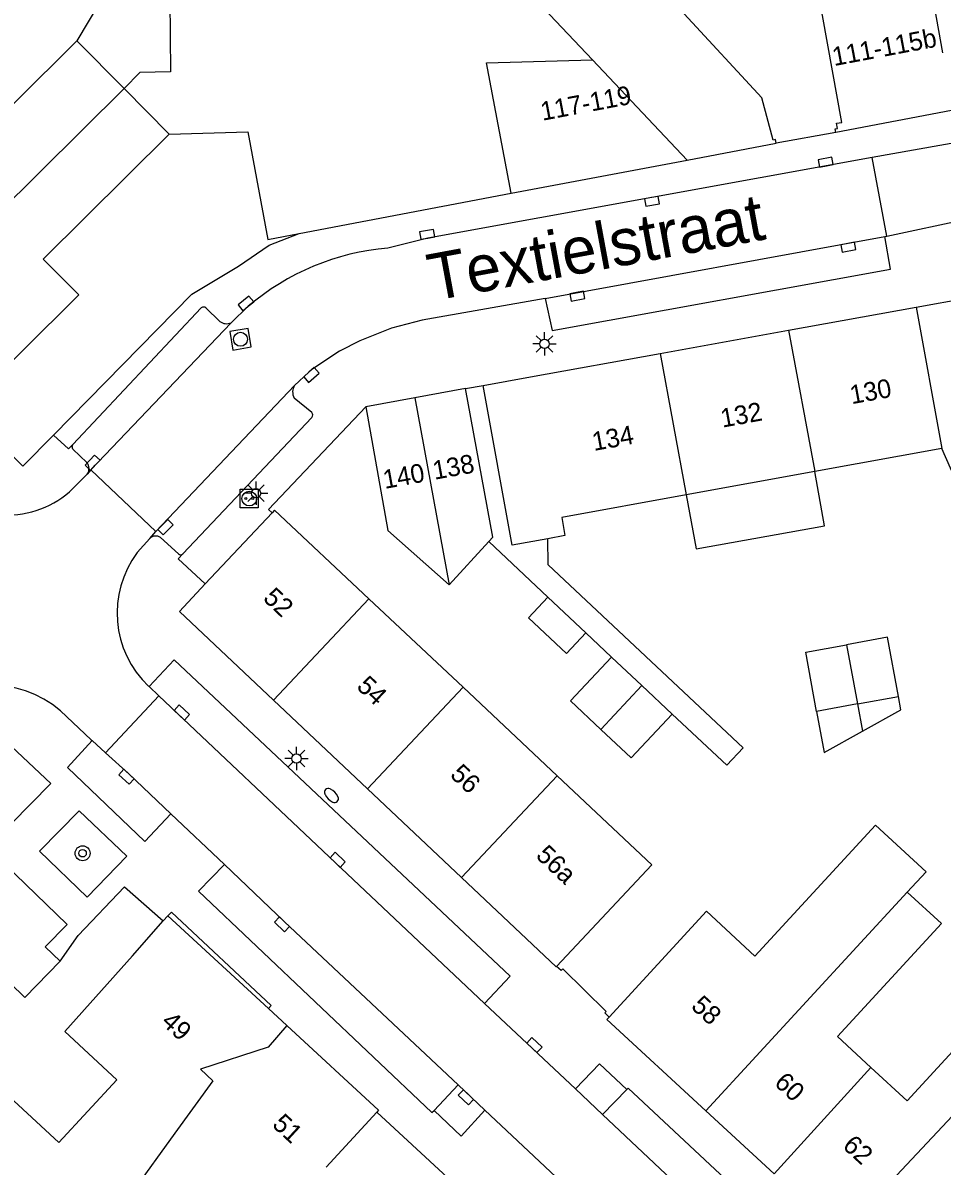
# Model space of a CAD drawing. Extents: x 132573 to 132944, y 398226 to 398676.
# Drawn here: x 132860.9 to 132910.1, y 398438.1 to 398499.2 of the extents above; entities that cross this region are included whole.
import ezdxf

# ---------------------------------------------------------------- set-up
doc = ezdxf.new("R2010")
doc.units = 0
for name, color, linetype in [('gg-afsc-erfafscheiding', 7, 'Continuous'), ('gg-afsc-hekwerk', 7, 'Continuous'), ('gg-afsc-muur', 7, 'Continuous'), ('gg-anno-huisnummerreeks BGT', 7, 'Continuous'), ('gg-anno-openbare ruimte label', 7, 'Continuous'), ('gg-bbg-bijgebouw', 7, 'Continuous'), ('gg-bbg-gedigitaliseerde bebouwing', 7, 'Continuous'), ('gg-bbg-gedigitaliseerde bijgebouw', 7, 'Continuous'), ('gg-bbg-hoofdgebouw', 7, 'Continuous'), ('gg-bbg-luifel en loopbrug', 7, 'Continuous'), ('gg-bbg-onder overbouw', 7, 'Continuous'), ('gg-bbg-pand overbouw', 7, 'Continuous'), ('gg-bbg-tussenscheiding', 7, 'Continuous'), ('gg-knt-verharding', 7, 'Continuous'), ('gg-knt-verharding nz', 7, 'Continuous'), ('gt-symb-boom', 7, 'Continuous'), ('gt-symb-brandkraan', 7, 'Continuous'), ('gt-symb-kolk', 7, 'Continuous'), ('gt-symb-laadpunt elektrisch vervoer', 7, 'Continuous'), ('gt-symb-lichtmast', 7, 'Continuous'), ('gt-symb-rioolschacht', 7, 'Continuous')]:
    doc.layers.add(name, color=color, linetype=linetype)

msp = doc.modelspace()

# ---------------------------------------------------------------- linework, layer by layer
at = {"layer": 'gg-afsc-erfafscheiding'}
for p, q in [((132885.847, 398471.471), (132889.016, 398468.493)), ((132891.044, 398466.589), (132892.425, 398465.291))]:
    msp.add_line(p, q, dxfattribs=at)
for points in [[(132938.989, 398469.328), (132915.384, 398464.55), (132915.077, 398465.165), (132910.089, 398476.44)], [(132895.67, 398462.243), (132898.589, 398459.5), (132899.462, 398460.43), (132889.031, 398470.23), (132889.003, 398471.619)]]:
    msp.add_lwpolyline(points, dxfattribs=at)
at = {"layer": 'gg-afsc-hekwerk'}
msp.add_line((132892.131, 398446.333), (132889.815, 398448.622), dxfattribs=at)
msp.add_lwpolyline([(132863.871, 398450.406), (132866.355, 398452.999), (132868.421, 398451.178)], dxfattribs=at)
at = {"layer": 'gg-afsc-muur'}
msp.add_line((132862.909, 398449.025), (132863.871, 398450.406), dxfattribs=at)
for points in [[(132874.252, 398473.004), (132874.07, 398473.177), (132879.28, 398478.67)], [(132889.815, 398448.622), (132889.718, 398448.519), (132889.468, 398448.75)], [(132892.298, 398446.027), (132892.063, 398446.27), (132892.131, 398446.333)]]:
    msp.add_lwpolyline(points, dxfattribs=at)
at = {"layer": 'gg-bbg-bijgebouw'}
for p, q in [((132875.696, 398487.943), (132887.054, 398490.091)), ((132874.032, 398487.628), (132875.696, 398487.943)), ((132884.61, 398479.65), (132881.889, 398479.15)), ((132881.889, 398479.15), (132879.28, 398478.67)), ((132879.28, 398478.67), (132880.456, 398472.065))]:
    msp.add_line(p, q, dxfattribs=at)
at = {"layer": 'gg-bbg-gedigitaliseerde bebouwing'}
for p, q in [((132863.798, 398498.252), (132866.33, 398495.702)), ((132908.72, 398484.01), (132910.089, 398476.44)), ((132910.089, 398476.44), (132903.291, 398475.208)), ((132903.291, 398475.208), (132896.413, 398473.961)), ((132874.39, 398473.15), (132879.434, 398468.411)), ((132879.434, 398468.411), (132884.474, 398463.676)), ((132884.474, 398463.676), (132889.514, 398458.941))]:
    msp.add_line(p, q, dxfattribs=at)
for points in [[(132855.615, 398493.198), (132857.149, 398491.652), (132863.798, 398498.252)], [(132889.003, 398471.619), (132887.094, 398471.274), (132885.55, 398479.81)], [(132896.413, 398473.961), (132889.753, 398472.754), (132889.928, 398471.787), (132889.003, 398471.619)], [(132889.514, 398458.941), (132894.583, 398454.178), (132889.468, 398448.75)], [(132892.298, 398446.027), (132897.495, 398451.694), (132900.096, 398449.298), (132906.546, 398456.302), (132909.251, 398453.811), (132908.243, 398452.717)], [(132908.243, 398452.717), (132910.071, 398451.033), (132904.506, 398444.993), (132906.296, 398443.344)], [(132866.778, 398449.313), (132863.156, 398445.261), (132865.947, 398442.685)], [(132853.984, 398444.409), (132856.211, 398446.712), (132857.728, 398445.246), (132860.236, 398447.842), (132861.028, 398447.078), (132862.909, 398449.025)], [(132906.296, 398443.344), (132908.234, 398441.559), (132913.937, 398447.75), (132915.701, 398446.125)], [(132865.947, 398442.685), (132862.841, 398439.321), (132858.972, 398442.892), (132853.795, 398435.076), (132852.967, 398434.14)]]:
    msp.add_lwpolyline(points, dxfattribs=at)
at = {"layer": 'gg-bbg-gedigitaliseerde bijgebouw'}
for p, q in [((132880.456, 398472.065), (132883.729, 398469.147)), ((132883.729, 398469.147), (132885.847, 398471.471)), ((132892.425, 398465.291), (132894.047, 398463.767)), ((132894.047, 398463.767), (132895.67, 398462.243)), ((132905.584, 398462.78), (132903.395, 398462.376)), ((132905.584, 398462.78), (132907.774, 398463.184))]:
    msp.add_line(p, q, dxfattribs=at)
for points in [[(132868.782, 398500.461), (132868.822, 398496.592), (132867.181, 398496.546), (132866.33, 398495.702)], [(132868.753, 398493.263), (132872.948, 398493.381), (132874.032, 398487.628)], [(132885.847, 398471.471), (132886.063, 398471.708), (132884.61, 398479.65)], [(132907.774, 398463.184), (132907.188, 398466.356), (132904.999, 398465.952)], [(132903.395, 398462.376), (132902.81, 398465.548), (132904.999, 398465.952)], [(132892.425, 398465.291), (132890.217, 398462.941), (132891.839, 398461.416)], [(132895.67, 398462.243), (132893.462, 398459.892), (132891.839, 398461.416)]]:
    msp.add_lwpolyline(points, dxfattribs=at)
at = {"layer": 'gg-bbg-hoofdgebouw'}
for p, q in [((132909.704, 398500), (132910.135, 398497.605)), ((132896.463, 398491.871), (132901.235, 398492.774)), ((132887.054, 398490.091), (132896.463, 398491.871)), ((132901.895, 398482.773), (132908.72, 398484.01)), ((132895.017, 398481.526), (132901.895, 398482.773)), ((132888.084, 398480.269), (132895.017, 398481.526)), ((132885.55, 398479.81), (132888.084, 398480.269)), ((132874.39, 398473.15), (132874.252, 398473.004)), ((132874.252, 398473.004), (132870.681, 398469.201)), ((132874.335, 398462.983), (132879.366, 398458.239)), ((132879.366, 398458.239), (132884.397, 398453.494)), ((132863.28, 398450.99), (132859.956, 398454.208)), ((132884.397, 398453.494), (132889.45, 398448.73)), ((132866.778, 398449.313), (132868.421, 398451.178)), ((132868.421, 398451.178), (132868.67, 398451.46)), ((132868.67, 398451.46), (132874.057, 398446.488)), ((132889.45, 398448.73), (132889.468, 398448.75)), ((132874.057, 398446.488), (132875.041, 398445.58)), ((132892.16, 398445.9), (132892.298, 398446.027)), ((132892.16, 398445.9), (132897.465, 398441.015)), ((132877.14, 398438.01), (132879.866, 398440.959)), ((132897.465, 398441.015), (132901.114, 398437.654))]:
    msp.add_line(p, q, dxfattribs=at)
for points in [[(132910.93, 398494.91), (132910.98, 398494.59), (132904.422, 398493.346)], [(132857.78, 398478.58), (132863.91, 398484.66), (132862.01, 398486.57), (132868.753, 398493.263)], [(132874.335, 398462.983), (132869.3, 398467.73), (132870.681, 398469.201)], [(132863.28, 398450.99), (132862.118, 398449.79), (132862.909, 398449.025)], [(132875.041, 398445.58), (132879.95, 398441.05), (132879.866, 398440.959)]]:
    msp.add_lwpolyline(points, dxfattribs=at)
at = {"layer": 'gg-bbg-luifel en loopbrug'}
for p, q in [((132889.016, 398468.493), (132891.044, 398466.589)), ((132905.584, 398462.78), (132905.851, 398461.33))]:
    msp.add_line(p, q, dxfattribs=at)
for points in [[(132868.782, 398500.461), (132865.027, 398500.275), (132863.798, 398498.252)], [(132896.413, 398473.961), (132896.946, 398471.072), (132903.815, 398472.317), (132903.291, 398475.208)], [(132889.016, 398468.493), (132887.979, 398467.393), (132890.002, 398465.484), (132891.044, 398466.589)], [(132905.851, 398461.33), (132907.905, 398462.473), (132907.774, 398463.184)], [(132903.395, 398462.376), (132903.798, 398460.189), (132905.851, 398461.33)]]:
    msp.add_lwpolyline(points, dxfattribs=at)
at = {"layer": 'gg-bbg-onder overbouw'}
for points in [[(132904.422, 398493.346), (132904.388, 398493.537), (132904.506, 398493.558), (132904.463, 398493.843), (132904.75, 398493.886), (132903.474, 398500.903)], [(132901.235, 398492.774), (132901.192, 398492.963), (132901.075, 398492.936), (132900.469, 398495.203), (132896.299, 398499.682)]]:
    msp.add_lwpolyline(points, dxfattribs=at)
at = {"layer": 'gg-bbg-pand overbouw'}
msp.add_line((132904.422, 398493.346), (132901.235, 398492.774), dxfattribs=at)
at = {"layer": 'gg-bbg-tussenscheiding'}
for p, q in [((132891.398, 398497.229), (132888.777, 398500)), ((132896.463, 398491.871), (132891.398, 398497.229)), ((132866.33, 398495.702), (132853.457, 398482.937)), ((132868.753, 398493.263), (132866.33, 398495.702)), ((132901.895, 398482.773), (132903.291, 398475.208)), ((132895.017, 398481.526), (132896.413, 398473.961)), ((132881.889, 398479.15), (132883.729, 398469.147)), ((132874.335, 398462.983), (132879.434, 398468.411)), ((132904.999, 398465.952), (132905.584, 398462.78)), ((132879.366, 398458.239), (132884.474, 398463.676)), ((132891.839, 398461.416), (132894.047, 398463.767)), ((132884.397, 398453.494), (132889.514, 398458.941)), ((132897.465, 398441.015), (132908.243, 398452.717)), ((132904.67, 398434.38), (132915.701, 398446.125)), ((132906.296, 398443.344), (132901.114, 398437.654)), ((132869.048, 398439.823), (132863.633, 398432.327))]:
    msp.add_line(p, q, dxfattribs=at)
for points in [[(132887.054, 398490.091), (132885.734, 398497.07), (132891.398, 398497.229)], [(132875.041, 398445.58), (132874.051, 398444.431), (132870.426, 398443.253), (132871.077, 398442.632), (132869.048, 398439.823)]]:
    msp.add_lwpolyline(points, dxfattribs=at)
at = {"layer": 'gg-knt-verharding'}
for p, q in [((132911.097, 398492.846), (132906.375, 398492.008)), ((132907.157, 398487.801), (132906.375, 398492.008)), ((132907.157, 398487.801), (132911.811, 398488.804)), ((132907.05, 398487.777), (132907.157, 398487.801)), ((132908.72, 398484.01), (132911.61, 398484.53)), ((132870.465, 398483.963), (132863.586, 398476.659)), ((132871.455, 398483.236), (132870.709, 398483.97)), ((132872.056, 398483.173), (132872.978, 398484.047)), ((132875.459, 398479.82), (132876.226, 398480.524)), ((132884.61, 398479.65), (132885.55, 398479.81)), ((132876.387, 398478.363), (132875.436, 398479.144)), ((132876.384, 398478.11), (132869.472, 398470.802)), ((132864.364, 398475.077), (132863.421, 398474.123)), ((132868.042, 398472), (132864.563, 398475.307)), ((132867.714, 398471.635), (132868.042, 398472)), ((132867.043, 398470.879), (132867.714, 398471.635)), ((132868.279, 398471.68), (132869.24, 398470.803)), ((132867.65, 398463.731), (132867.672, 398463.71)), ((132867.672, 398463.71), (132868.19, 398463.22)), ((132865.338, 398460.177), (132868.19, 398463.22)), ((132864.577, 398460.867), (132864.621, 398460.827)), ((132864.621, 398460.827), (132865.338, 398460.177)), ((132868.844, 398456.904), (132871.705, 398454.19)), ((132885.629, 398446.771), (132890.49, 398442.194)), ((132884.216, 398442.405), (132882.924, 398441.047)), ((132884.216, 398442.405), (132885.643, 398441.063)), ((132890.49, 398442.194), (132891.944, 398440.824)), ((132893.233, 398442.169), (132891.944, 398440.824)), ((132885.643, 398441.063), (132890.02, 398436.944))]:
    msp.add_line(p, q, dxfattribs=at)
for points in [[(132906.375, 398492.008), (132882.59, 398487.7), (132880.449, 398487.163)], [(132872.455, 398486.189), (132874.105, 398487.319), (132875.696, 398487.943)], [(132888.865, 398484.466), (132889.249, 398482.762), (132907.344, 398486.029), (132907.05, 398487.777)], [(132862.552, 398477.162), (132869.968, 398484.699), (132872.455, 398486.189)], [(132888.865, 398484.466), (132882.285, 398483.312), (132880.639, 398482.871), (132878.957, 398482.207), (132877.859, 398481.647), (132876.389, 398480.667), (132876.226, 398480.524)], [(132857.78, 398478.58), (132860.91, 398475.497), (132862.552, 398477.162)], [(132862.552, 398477.162), (132863.365, 398476.424), (132863.586, 398476.659)], [(132864.337, 398475.694), (132863.596, 398476.417), (132863.562, 398476.538), (132863.586, 398476.659)], [(132870.681, 398469.201), (132869.23, 398470.547), (132869.472, 398470.802)], [(132868.19, 398463.22), (132877.627, 398454.301), (132885.629, 398446.771)], [(132860.299, 398456.375), (132862.406, 398458.53), (132859.999, 398460.795), (132857.937, 398458.694), (132860.299, 398456.375)], [(132865.338, 398460.177), (132866.598, 398459.035), (132868.844, 398456.904)], [(132861.813, 398454.908), (132864.351, 398452.452), (132866.488, 398454.635), (132863.935, 398457.065), (132861.813, 398454.908)], [(132871.705, 398454.19), (132874.922, 398451.138), (132884.216, 398442.405)], [(132874.057, 398446.488), (132874.203, 398446.647), (132868.88, 398451.644), (132868.67, 398451.46)], [(132890.49, 398442.194), (132891.77, 398443.535), (132893.233, 398442.169)], [(132886.627, 398434.629), (132885.53, 398435.616), (132885.581, 398435.671), (132885.532, 398435.717), (132879.866, 398440.959)], [(132882.924, 398441.047), (132884.371, 398439.675), (132885.643, 398441.063)], [(132891.944, 398440.824), (132898.699, 398434.461), (132909.279, 398424.572), (132913.002, 398421.114)]]:
    msp.add_lwpolyline(points, dxfattribs=at)
for centre, radius, start, end in [((132881.565, 398473.972), 13.238, 94.83774, 130.44229), ((132870.592, 398483.798), 0.208, 55.6758, 127.61076), ((132871.809, 398483.715), 0.596, 233.55554, 294.47608), ((132876.019, 398479.463), 0.665, 147.46265, 208.64003), ((132876.218, 398478.238), 0.21, 322.18693, 36.45434), ((132863.97, 398475.369), 0.49, 323.45298, 41.55836), ((132868.022, 398471.336), 0.429, 53.24127, 135.86626), ((132869.357, 398470.928), 0.171, 226.91933, 312.58674)]:
    msp.add_arc(centre, radius, start, end, dxfattribs=at)
at = {"layer": 'gg-knt-verharding nz'}
for p, q in [((132888.865, 398484.466), (132907.05, 398487.777)), ((132872.056, 398483.173), (132864.563, 398475.307)), ((132875.459, 398479.82), (132868.042, 398472)), ((132864.563, 398475.307), (132864.364, 398475.077)), ((132862.939, 398462.411), (132864.577, 398460.867))]:
    msp.add_line(p, q, dxfattribs=at)
for points in [[(132867.672, 398463.71), (132869.022, 398465.145), (132886.996, 398448.223), (132885.629, 398446.771)], [(132864.621, 398460.827), (132863.298, 398459.385), (132867.45, 398455.427), (132868.844, 398456.904)], [(132871.705, 398454.19), (132870.32, 398452.762), (132882.811, 398440.928), (132882.924, 398441.047)], [(132893.233, 398442.169), (132893.303, 398442.226), (132914.365, 398422.567), (132914.284, 398422.48)]]:
    msp.add_lwpolyline(points, dxfattribs=at)
for centre, radius, start, end in [((132860.082, 398478.019), 5.131, 218.82478, 310.59907), ((132871.328, 398467.643), 5.37, 142.94314, 226.76456), ((132859.156, 398457.971), 5.833, 49.56638, 133.50414)]:
    msp.add_arc(centre, radius, start, end, dxfattribs=at)
at = {"layer": 'gt-symb-boom'}
for radius in [0.4, 0.2]:
    msp.add_circle((132864.113, 398454.798), radius, dxfattribs=at)
at = {"layer": 'gt-symb-brandkraan'}
for centre, radius, start, end in [((132877.259, 398458.06), 0.206, 61.60831, 206.47444), ((132879.761, 398459.306), 3, 206.47444, 207.14934), ((132877.926, 398458.365), 0.938, 207.14934, 240.9334), ((132875.931, 398455.602), 3, 60.93342, 61.60831), ((132876.932, 398457.405), 0.938, 27.14933, 60.93342), ((132877.599, 398457.71), 0.206, 241.60829, 26.47443), ((132875.097, 398456.464), 3, 26.47443, 27.14933), ((132878.927, 398460.168), 3, 240.9334, 241.60829)]:
    msp.add_arc(centre, radius, start, end, dxfattribs=at)
at = {"layer": 'gt-symb-kolk'}
for points in [[(132903.916, 398491.562), (132904.285, 398491.629), (132904.214, 398492.022), (132903.476, 398491.889), (132903.547, 398491.495), (132903.916, 398491.562)], [(132894.552, 398489.862), (132894.183, 398489.795), (132894.255, 398489.401), (132894.993, 398489.536), (132894.921, 398489.929), (132894.552, 398489.862)], [(132882.59, 398487.7), (132882.959, 398487.767), (132882.888, 398488.16), (132882.15, 398488.027), (132882.221, 398487.633), (132882.59, 398487.7)], [(132905.06, 398487.411), (132904.691, 398487.344), (132904.763, 398486.95), (132905.501, 398487.085), (132905.429, 398487.478), (132905.06, 398487.411)], [(132890.552, 398484.781), (132890.183, 398484.712), (132890.257, 398484.319), (132890.994, 398484.457), (132890.921, 398484.85), (132890.552, 398484.781)], [(132872.978, 398484.047), (132873.269, 398484.284), (132873.016, 398484.594), (132872.435, 398484.12), (132872.687, 398483.81), (132872.978, 398484.047)], [(132876.226, 398480.524), (132875.946, 398480.275), (132876.212, 398479.976), (132876.772, 398480.475), (132876.506, 398480.773), (132876.226, 398480.524)], [(132864.791, 398475.547), (132865.05, 398475.818), (132864.76, 398476.094), (132864.243, 398475.551), (132864.532, 398475.276), (132864.791, 398475.547)], [(132868.407, 398472.377), (132868.146, 398472.108), (132868.433, 398471.829), (132868.955, 398472.368), (132868.668, 398472.646), (132868.407, 398472.377)], [(132869.287, 398462.181), (132869.559, 398461.923), (132869.834, 398462.214), (132869.29, 398462.729), (132869.015, 398462.439), (132869.287, 398462.181)], [(132866.598, 398459.035), (132866.32, 398459.287), (132866.052, 398458.99), (132866.607, 398458.487), (132866.876, 398458.783), (132866.598, 398459.035)], [(132877.627, 398454.301), (132877.9, 398454.043), (132878.174, 398454.334), (132877.629, 398454.849), (132877.354, 398454.559), (132877.627, 398454.301)], [(132874.922, 398451.138), (132874.65, 398451.396), (132874.375, 398451.106), (132874.919, 398450.59), (132875.194, 398450.88), (132874.922, 398451.138)], [(132888.157, 398444.392), (132888.43, 398444.135), (132888.704, 398444.426), (132888.158, 398444.94), (132887.884, 398444.649), (132888.157, 398444.392)], [(132884.764, 398441.89), (132884.491, 398442.147), (132884.217, 398441.855), (132884.763, 398441.342), (132885.037, 398441.633), (132884.764, 398441.89)]]:
    msp.add_lwpolyline(points, dxfattribs=at)
at = {"layer": 'gt-symb-laadpunt elektrisch vervoer'}
msp.add_lwpolyline([(132872.546, 398474.267), (132873.518, 398474.267), (132873.518, 398473.267), (132872.546, 398473.267)], close=True, dxfattribs=at)
for centre, radius in [((132873.032, 398473.766), 0.393), ((132872.846, 398473.766), 0.0566), ((132873.218, 398473.766), 0.0566)]:
    msp.add_circle(centre, radius, dxfattribs=at)
at = {"layer": 'gt-symb-lichtmast'}
for p, q in [((132888.655, 398482.212), (132888.39, 398482.477)), ((132888.832, 398482.285), (132888.832, 398482.66)), ((132889.009, 398482.212), (132889.274, 398482.477)), ((132888.582, 398482.035), (132888.207, 398482.035)), ((132888.655, 398481.858), (132888.39, 398481.593)), ((132888.832, 398481.785), (132888.832, 398481.41)), ((132889.274, 398481.593), (132889.009, 398481.858)), ((132889.082, 398482.035), (132889.457, 398482.035)), ((132873.218, 398474.227), (132872.953, 398474.492)), ((132873.395, 398474.3), (132873.395, 398474.675)), ((132873.572, 398474.227), (132873.837, 398474.492)), ((132873.145, 398474.05), (132872.77, 398474.05)), ((132873.218, 398473.873), (132872.953, 398473.608)), ((132873.395, 398473.8), (132873.395, 398473.425)), ((132873.837, 398473.608), (132873.572, 398473.873)), ((132873.645, 398474.05), (132874.02, 398474.05)), ((132875.383, 398460.038), (132875.118, 398460.303)), ((132875.56, 398460.111), (132875.56, 398460.486)), ((132875.737, 398460.038), (132876.002, 398460.303)), ((132875.31, 398459.861), (132874.935, 398459.861)), ((132875.383, 398459.684), (132875.118, 398459.419)), ((132876.002, 398459.419), (132875.737, 398459.684)), ((132875.81, 398459.861), (132876.185, 398459.861)), ((132875.56, 398459.611), (132875.56, 398459.236))]:
    msp.add_line(p, q, dxfattribs=at)
for centre in [(132888.832, 398482.035), (132873.395, 398474.05), (132875.56, 398459.861)]:
    msp.add_circle(centre, 0.25, dxfattribs=at)
at = {"layer": 'gt-symb-rioolschacht'}
msp.add_lwpolyline([(132872.156, 398481.708), (132873.142, 398481.874), (132872.976, 398482.86), (132871.99, 398482.694)], close=True, dxfattribs=at)
msp.add_circle((132872.566, 398482.284), 0.375, dxfattribs=at)

# ---------------------------------------------------------------- texts
at = {"layer": 'gg-anno-huisnummerreeks BGT'}
for s, rotation, p in [('111-115b', 10.7, (132904.33, 398496.893)), ('117-119', 10.7, (132888.722, 398493.969)), ('130', 10.3, (132905.269, 398478.811)), ('132', 10.3, (132898.353, 398477.557)), ('134', 10.3, (132891.476, 398476.31)), ('138', 10.4, (132882.946, 398474.769)), ('140', 10.4, (132880.285, 398474.28)), ('52', 316.7, (132873.718, 398468.375)), ('54', 316.7, (132878.724, 398463.654)), ('56', 316.7, (132883.728, 398458.935)), ('56a', 316.7, (132888.317, 398454.609)), ('58', 317.4, (132896.622, 398446.549)), ('49', 317.3, (132868.269, 398445.707)), ('60', 317.4, (132901.074, 398442.448)), ('51', 317.3, (132874.207, 398440.226)), ('62', 317.4, (132904.731, 398439.082))]:
    msp.add_text(s, height=1, rotation=rotation, dxfattribs=at).set_placement(p)
at = {"layer": 'gg-anno-openbare ruimte label'}
msp.add_text('Textielstraat', height=2.5, rotation=10.5, dxfattribs=at).set_placement((132882.846, 398484.327))

doc.saveas('drawing.dxf')
